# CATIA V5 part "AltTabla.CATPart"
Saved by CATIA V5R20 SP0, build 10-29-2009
Part number: Part1.2
Bounding box of the stored display mesh (mm): x -10 to 15, y -89.812 to 89.812, z -89.687 to 89.687
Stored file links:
  C:\Users\metin\Desktop\CatiaDers\AltTabla.CATPart
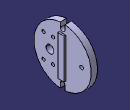
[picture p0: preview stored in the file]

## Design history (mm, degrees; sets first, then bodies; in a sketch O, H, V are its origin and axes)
Body1 (main body)
  Sketch1 on yz-plane, origin (0, 0, 0), H (0, 1, 0), V (0, 0, 1)
    arc A1 centre (0, 0) radius 90 from (-7.5, 89.687) to (-7.5, -89.687) ccw
    circle A2 centre (-40, 0) radius 12.5
    point P1 (-40, 0)
    arc A3 centre (0, 75) radius 7.5 from (-7.5, 75) to (7.5, 75) ccw
    point P2 (0, 75)
    line L1 (-7.5, 75) -> (-7.5, 89.687)
    point P3 (-7.5, 75)
    point P4 (-7.5, 89.687)
    line L2 (7.5, 75) -> (7.5, 89.687)
    point P5 (7.5, 75)
    point P6 (7.5, 89.687)
    point P7 (-7.5, 75)
    point P8 (7.5, 75)
    point P9 (7.5, -75)
    point P10 (-7.5, -75)
    point P11 (0, -75)
    arc A4 centre (0, -75) radius 7.5 from (-7.5, -75) to (7.5, -75) cw
    point P12 (7.5, -89.687)
    point P13 (7.5, -75)
    line L3 (7.5, -75) -> (7.5, -89.687)
    point P14 (-7.5, -89.687)
    point P15 (-7.5, -75)
    line L4 (-7.5, -75) -> (-7.5, -89.687)
    arc A5 centre (0, 0) radius 90 from (7.5, -89.687) to (7.5, 89.687) ccw
    circle A6 centre (-60, 37.5) radius 5
    point P17 (-60, 37.5)
    point P18 (-60, -37.5)
    circle A7 centre (-60, -37.5) radius 5
    radius A1 = 90
    radius A2 = 12.5
    distance P1 V = 40
    radius A3 = 7.5
    distance P2 P11 = 150
    radius A6 = 5
    distance P17 P18 = 75
    distance P17 V = 60
    coincidence: P1 H, P2 V, P3 A3, P5 A3, L2 P8, L1 P7, A1 A5, P3 P7, P5 P8, P9 P13, P10 P15
    concentricity: A1 O
    tangency: L1 A3, L2 A3
    symmetry: P8 P9 H, P7 P10 H, A3 A4 H, P6 P12 H, P5 P13 H, L2 L3 H, P4 P14 H, P3 P15 H, L1 L4 H, A6 A7 H
    vertical: L2 V, L1 V, L4 V, L3 V
  Pad1: profile Sketch1, direction (1, 0, 0), length 10, mirrored extent
  Sketch2 on end face of Pad1, origin (10, 28.3984, 6.9494), H (0, 1, 0), V (0, 0, 1)
    point P1 (31.6016, -6.9494)
    reference intersected line E1 through (-28.3984, 0) direction (0, 1) from zx-plane
    reference intersected line E2 through (0, -6.9494) direction (-1, 0) from xy-plane
    distance P1 E1 = 60
    distance P1 E2 = 0
  Hole1: placed by Sketch2, at (10, 60, 0) direction (-1, 0, 0), diameter 12, through (limit type 3)
  Sketch3 on end face of Pad1, origin (10, -35.9389, 50.0143), H (0, 1, 0), V (0, 0, 1)
    point P1 (5.9389, -12.5143)
    reference intersected line E1 through (0, -50.0143) direction (-1, 0) from xy-plane
    reference intersected line E2 through (35.9389, 0) direction (0, 1) from zx-plane
    distance P1 E1 = 37.5
    distance P1 E2 = 30
  Hole2: placed by Sketch3, at (10, -30, 37.5) direction (-1, 0, 0), diameter 10, through (limit type 3)
  Mirror1: of Hole2, about xy-plane
  Sketch4 on end face of Pad1, origin (10, 0, 0), H (0, 1, 0), V (0, 0, 1)
    line L1 (-10, 62.5) -> (10, 62.5)
    line L2 (10, 62.5) -> (10, -62.5)
    line L3 (10, -62.5) -> (-10, -62.5)
    line L4 (-10, -62.5) -> (-10, 62.5)
    distance L1 L3 = 125
    distance L4 L2 = 20
    horizontal: L1 H, L3 H
    vertical: L2 V, L4 V
    symmetry: L2 L4 V, L3 L1 H
  Pad2: profile Sketch4, direction (1, 0, 0), length 5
